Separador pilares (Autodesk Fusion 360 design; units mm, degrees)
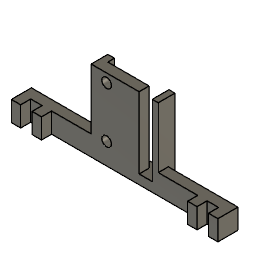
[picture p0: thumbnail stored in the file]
part number: 2026-07-18-00-36-45-634
sketch "Boceto1" plane through (0, 0, 0) normal (0, 0, 1) x axis (1, 0, 0)
  line L1 (0, 6) -> (0, 0)
  line L2 (55.5, 6) -> (0, 6)
  line L3 (55.5, 0) -> (55.5, 6)
  line L4 (58.5, 0) -> (55.5, 0)
  line L5 (58.5, 3) -> (58.5, 0)
  line L6 (58.5, 6) -> (58.5, 3)
  line L7 (55.5, 6) -> (58.5, 6)
  line L8 (55.5, 3) -> (55.5, 0)
  line L9 (0, 3) -> (55.5, 3)
  line L10 (-3, 0) -> (0, 0)
  line L11 (-3, 6) -> (-3, 0)
  line L12 (-3, 6) -> (0, 6)
  line L13 (52.5, 3) -> (55.5, 3)
  line L14 (52.5, 0) -> (52.5, 3)
  line L15 (49.5, 0) -> (52.5, 0)
  line L16 (49.5, 3) -> (49.5, 0)
  line L17 (3, 3) -> (0, 3)
  line L18 (3, 0) -> (3, 3)
  line L19 (6, 0) -> (3, 0)
  line L20 (6, 3) -> (6, 0)
  point P1 (0, 0)
  point P2 (0, 0)
  point P9 (55.5, 3)
  point P10 (0, 3)
  point P16 (49.5, 3)
  point P17 (3, 3)
  point P20 (6, 3)
  point P3 (0, 6)
  point P4 (55.5, 6)
  point P5 (55.5, 0)
  point P6 (58.5, 0)
  point P13 (52.5, 3)
  point P14 (52.5, 0)
  point P15 (49.5, 0)
  coincident P1 P2
  vertical L1
  perpendicular L1 L2
  perpendicular L2 L3
  perpendicular L3 L4
  perpendicular L4 L5
  perpendicular L4 L6
  midpoint L3 P9
  midpoint L1 P10
  perpendicular L1 L9
  perpendicular L1 L10
  perpendicular L10 L11
  perpendicular L3 L13
  perpendicular L13 L14
  perpendicular L14 L15
  coincident L9 P16
  perpendicular L9 L16
  coincident L9 P17
  perpendicular L17 L18
  perpendicular L18 L19
  coincident L9 P20
  perpendicular L9 L20
  dimension "d1" distance P2 P3 = 6
  dimension "d2" distance P3 P4 = 55.5
  dimension "d3" distance P5 P6 = 3
  dimension "d4" distance P9 P13 = 3
  dimension "d5" distance P14 P15 = 3
extrude "Extruir1" new body sketch "Boceto1" along normal blind 6
sketch "Boceto2" plane through (0, 0, 6) normal (0, 0, 1) x axis (-1, 0, 0)
  line L1 (0, -3) -> (0, 0)
  line L2 (-3, -3) -> (0, -3)
  line L3 (-3, 0) -> (-3, -3)
  line L4 (-6, 0) -> (-3, 0)
  line L5 (-6, -3) -> (-6, 0)
  line L6 (-49.5, -3) -> (-6, -3)
  line L7 (-49.5, 0) -> (-49.5, -3)
  line L8 (-52.5, 0) -> (-49.5, 0)
  line L9 (-52.5, -3) -> (-52.5, 0)
  line L10 (-55.5, -3) -> (-52.5, -3)
  line L11 (-55.5, 0) -> (-55.5, -3)
  line L12 (-58.5, 0) -> (-55.5, 0)
  line L13 (-58.5, -6) -> (-58.5, 0)
  line L14 (-55.5, -6) -> (-58.5, -6)
  line L15 (0, -6) -> (-55.5, -6)
  line L16 (3, -6) -> (0, -6)
  line L17 (3, 0) -> (3, -6)
  line L18 (0, 0) -> (3, 0)
  line L19 (-19.75, -6) -> (-27.75, -6)
  line L20 (-19.75, -9) -> (-19.75, -6)
  line L21 (-16.75, -9) -> (-19.75, -9)
  line L22 (-16.75, -6) -> (-16.75, -9)
  line L23 (-35.75, -6) -> (-27.75, -6)
  line L24 (-35.75, -9) -> (-35.75, -6)
  line L25 (-38.75, -9) -> (-35.75, -9)
  line L26 (-38.75, -6) -> (-38.75, -9)
  point P20 (-27.75, -6)
  point P24 (-16.75, -6)
  point P28 (-38.75, -6)
  point P21 (-19.75, -6)
  point P22 (-19.75, -9)
  point P23 (-16.75, -9)
  point P25 (-35.75, -6)
  point P26 (-35.75, -9)
  point P27 (-38.75, -9)
  midpoint L15 P20
  parallel L15 L19
  perpendicular L19 L20
  perpendicular L20 L21
  coincident L15 P24
  perpendicular L15 L22
  perpendicular L22 L23
  perpendicular L23 L24
  perpendicular L24 L25
  coincident L15 P28
  perpendicular L15 L26
  dimension "d8" distance P20 P21 = 8
  dimension "d9" distance P22 P23 = 3
  dimension "d10" distance P20 P25 = 8
  dimension "d11" distance P26 P27 = 3
extrude "Extruir2" add sketch "Boceto2" profile of L15 L20 L21 L22 L24 L25 L26 against normal blind 6
sketch "Boceto3" plane through (0, 0, 6) normal (0, 0, 1) x axis (-1, 0, 0)
  line L1 (0, -3) -> (0, 0)
  line L2 (-3, -3) -> (0, -3)
  line L3 (-3, 0) -> (-3, -3)
  line L4 (-6, 0) -> (-3, 0)
  line L5 (-6, -3) -> (-6, 0)
  line L6 (-49.5, -3) -> (-6, -3)
  line L7 (-49.5, 0) -> (-49.5, -3)
  line L8 (-52.5, 0) -> (-49.5, 0)
  line L9 (-52.5, -3) -> (-52.5, 0)
  line L10 (-55.5, -3) -> (-52.5, -3)
  line L11 (-55.5, 0) -> (-55.5, -3)
  line L12 (-58.5, 0) -> (-55.5, 0)
  line L13 (-58.5, -6) -> (-58.5, 0)
  line L14 (-55.5, -6) -> (-58.5, -6)
  line L15 (-38.75, -6) -> (-55.5, -6)
  line L16 (-38.75, -9) -> (-38.75, -6)
  line L17 (-35.75, -9) -> (-38.75, -9)
  line L18 (-35.75, -6) -> (-35.75, -9)
  line L19 (-19.75, -6) -> (-35.75, -6)
  line L20 (-19.75, -9) -> (-19.75, -6)
  line L21 (-16.75, -9) -> (-19.75, -9)
  line L22 (-16.75, -6) -> (-16.75, -9)
  line L23 (0, -6) -> (-16.75, -6)
  line L24 (3, -6) -> (0, -6)
  line L25 (3, 0) -> (3, -6)
  line L26 (0, 0) -> (3, 0)
  line L27 (-38.75, -3) -> (-38.75, -9)
  line L28 (-16.75, -3) -> (-16.75, -9)
  line L29 (-38.75, -3) -> (-16.75, -3)
  line L30 (-35.75, -9) -> (-38.75, -9)
  line L31 (-35.75, -6) -> (-35.75, -9)
  line L32 (-19.75, -6) -> (-35.75, -6)
  line L33 (-19.75, -9) -> (-19.75, -6)
  line L34 (-16.75, -9) -> (-19.75, -9)
  point P18 (-38.75, -9)
  point P28 (-38.75, -9)
  point P29 (-38.75, -3)
  point P23 (-16.75, -9)
  point P30 (-16.75, -9)
  point P31 (-16.75, -3)
  point P19 (-35.75, -9)
  point P32 (-35.75, -9)
  point P20 (-35.75, -6)
  point P33 (-35.75, -6)
  point P34 (-35.75, -6)
  point P21 (-19.75, -6)
  point P35 (-19.75, -6)
  point P36 (-19.75, -6)
  point P22 (-19.75, -9)
  point P37 (-19.75, -9)
  point P38 (-16.75, -9)
  coincident P18 P28
  coincident L6 P29
  perpendicular L6 L27
  coincident P23 P30
  coincident L6 P31
  perpendicular L6 L28
  coincident P19 P32
  coincident P20 P33
  coincident P20 P34
  coincident P21 P35
  coincident P21 P36
  coincident P22 P37
  coincident P23 P38
extrude "Extruir3" add sketch "Boceto3" profile of L6 L16 L17 L18 L19 L20 L21 L22 L27 L28 L29 L30 L31 L32 L33 L34 along normal blind 15
sketch "Boceto4" plane through (0, 6, 0) normal (0, 1, 0) x axis (-1, 0, 0)
  line L1 (-35.75, 0) -> (-35.75, 21)
  line L2 (-19.75, 0) -> (-35.75, 0)
  line L3 (-19.75, 21) -> (-19.75, 0)
  line L4 (-35.75, 21) -> (-19.75, 21)
  line L5 (-34.546, 21) -> (-35.75, 21)
  line L6 (-33.114, 21) -> (-34.546, 21)
  line L7 (-33.114, 19.886) -> (-33.114, 21)
  line L8 (-33.114, 18.454) -> (-33.114, 19.886)
  line L9 (-33.114, 3.393) -> (-33.114, 18.454)
  line L10 (-20.954, 21) -> (-19.75, 21)
  line L11 (-22.386, 21) -> (-20.954, 21)
  line L12 (-22.386, 19.886) -> (-22.386, 21)
  line L13 (-22.386, 18.454) -> (-22.386, 19.886)
  line L14 (-22.386, 3.393) -> (-22.386, 18.454)
  circle C1 centre (-33.114, 18.454) radius 1.4325
  circle C2 centre (-33.114, 3.393) radius 1.4325
  circle C3 centre (-22.386, 18.454) radius 1.4325
  circle C4 centre (-22.386, 3.393) radius 1.4325
  point P2 (-35.75, 21)
  point P6 (-35.75, 21)
  point P10 (-33.114, 18.454)
  point P11 (-33.114, 18.454)
  point P12 (-33.114, 3.393)
  point P13 (-33.114, 3.393)
  point P5 (-19.75, 21)
  point P14 (-19.75, 21)
  point P18 (-22.386, 18.454)
  point P19 (-22.386, 18.454)
  point P20 (-22.386, 3.393)
  point P21 (-22.386, 3.393)
  point P7 (-34.546, 21)
  point P8 (-33.114, 21)
  point P9 (-33.114, 19.886)
  point P15 (-20.954, 21)
  point P16 (-22.386, 21)
  point P17 (-22.386, 19.886)
  coincident P2 P6
  perpendicular L1 L5
  parallel L4 L6
  perpendicular L6 L7
  perpendicular L5 L8
  coincident P10 P11
  parallel L8 L9
  coincident P12 P13
  coincident P5 P14
  perpendicular L3 L10
  parallel L4 L11
  perpendicular L4 L12
  parallel L12 L13
  coincident P18 P19
  vertical L14
  coincident P20 P21
  dimension "d16" distance P6 P7 = 1.204
  dimension "d17" distance P7 P8 = 1.432
  dimension "d18" distance P8 P9 = 1.114
  dimension "d19" distance P9 P10 = 1.432
  dimension "d20" diameter C1 = 2.865
  dimension "d21" distance P10 P12 = 15.061
  dimension "d22" diameter C2 = 2.865
  dimension "d23" distance P14 P15 = 1.204
  dimension "d24" distance P15 P16 = 1.432
  dimension "d25" distance P16 P17 = 1.114
  dimension "d26" distance P17 P18 = 1.432
  dimension "d27" diameter C3 = 2.865
  dimension "d28" distance P18 P20 = 15.061
  dimension "d29" diameter C4 = 2.865
extrude "Extruir4" cut sketch "Boceto4" profile of L12 L13 C3 L14 C4 against normal blind 6
extrude "Extruir5" add of existing geometry blind 3
extrude "Extruir6" cut of existing geometry blind -3
sketch "Boceto5" plane through (19.75, 0, 0) normal (1, 0, 0) x axis (0, 1, 0)
  line L1 (6, -3) -> (6, 21)
  line L2 (9, -3) -> (6, -3)
  line L3 (9, 21) -> (9, -3)
  line L4 (6, 21) -> (9, 21)
  line L5 (9, -3) -> (6, -3)
  line L6 (9, 0) -> (9, -3)
  line L7 (6, 0) -> (9, 0)
  line L8 (6, -3) -> (6, 0)
  point P3 (6, -3)
  point P6 (6, -3)
  point P4 (9, -3)
  point P7 (9, -3)
  point P8 (9, -3)
  point P9 (9, 0)
  point P10 (6, 0)
  coincident P3 P6
  coincident P4 P7
  coincident P4 P8
  coincident L3 P9
  coincident L1 P10
  perpendicular L1 L7
extrude "Extruir7" add sketch "Boceto5" profile of L1 L2 L3 L5 L6 L7 L8 along normal blind 16
sketch "Boceto6" plane through (0, 0, 21) normal (0, 0, 1) x axis (-1, 0, 0)
  line L1 (-35.75, -9) -> (-38.75, -9)
  line L2 (-35.75, -6) -> (-35.75, -9)
  line L3 (-19.75, -6) -> (-35.75, -6)
  line L4 (-19.75, -9) -> (-19.75, -6)
  line L5 (-16.75, -9) -> (-19.75, -9)
  line L6 (-16.75, -3) -> (-16.75, -9)
  line L7 (-38.75, -3) -> (-16.75, -3)
  line L8 (-38.75, -9) -> (-38.75, -3)
  line L9 (-35.75, -3) -> (-35.75, -6)
  line L10 (-32.25, -3) -> (-35.75, -3)
  line L11 (-32.25, -6) -> (-32.25, -3)
  line L12 (-35.75, -6) -> (-32.25, -6)
  point P4 (-35.75, -6)
  point P10 (-35.75, -6)
  point P11 (-35.75, -3)
  point P13 (-32.25, -6)
  point P14 (-35.75, -6)
  point P12 (-32.25, -3)
  coincident P4 P10
  coincident L7 P11
  perpendicular L7 L9
  perpendicular L9 L10
  coincident L3 P13
  perpendicular L3 L11
  coincident P4 P14
  dimension "d38" distance P11 P12 = 3.5
extrude "Extruir8" cut sketch "Boceto6" profile of L3 L7 L9 L10 L11 L12 to an object
extrude "Extruir9" cut of existing geometry blind -1
extrude "Extruir10" cut of existing geometry blind -1
extrude "Extruir11" cut of existing geometry blind -1
extrude "Extruir12" cut of existing geometry blind -0.2
extrude "Extruir13" cut of existing geometry blind -0.2
extrude "Extruir14" cut of existing geometry blind -0.2
extrude "Extruir15" cut of existing geometry blind -0.2
extrude "Extruir16" cut of existing geometry blind -0.2
extrude "Extruir17" cut of existing geometry blind -0.2
extrude "Extruir18" cut of existing geometry blind -0.2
